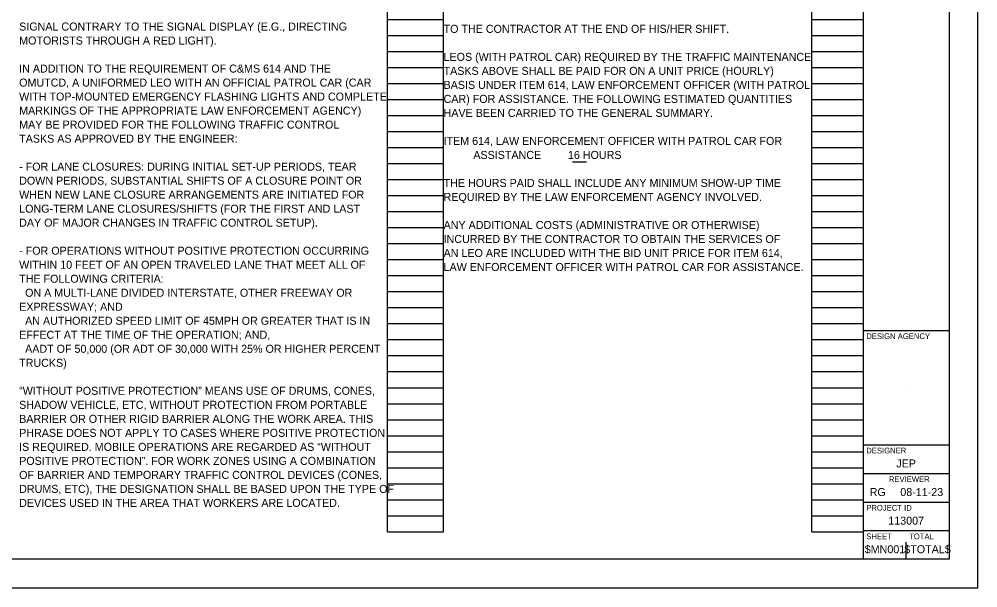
# Model space of a CAD drawing. Extents: x 0 to 69, y 0 to 22.
# Drawn here: x 17.24 to 34, y 0 to 9.94 of the extents above; entities that cross this region are included whole.
import ezdxf

# ---------------------------------------------------------------- set-up
doc = ezdxf.new("R2010")
doc.units = 0
for name, color, linetype in [('GM_X_City_Street', 7, 'Continuous'), ('GM_X_Corporation_Text', 7, 'Continuous'), ('SH_Border', 7, 'Continuous'), ('SH_Cut_Line', 7, 'Continuous'), ('SH_Data', 7, 'Continuous'), ('SH_Text', 7, 'Continuous')]:
    doc.layers.add(name, color=color, linetype=linetype)

msp = doc.modelspace()

# ---------------------------------------------------------------- linework, layer by layer
at = {"layer": 'GM_X_City_Street'}
for p, q in [((23.68, 0.98), (23.68, 21.14)), ((24.66, 0.98), (24.66, 21.14)), ((31.1, 0.98), (31.1, 21.14)), ((32, 0.98), (32, 21.14)), ((23.68, 9.94), (24.66, 9.94)), ((31.1, 9.94), (32, 9.94)), ((23.68, 9.66), (24.66, 9.66)), ((31.1, 9.66), (32, 9.66)), ((23.68, 9.38), (24.66, 9.38)), ((31.1, 9.38), (32, 9.38)), ((23.68, 9.1), (24.66, 9.1)), ((31.1, 9.1), (32, 9.1)), ((23.68, 8.82), (24.66, 8.82)), ((31.1, 8.82), (32, 8.82)), ((23.68, 8.54), (24.66, 8.54)), ((31.1, 8.54), (32, 8.54)), ((23.68, 8.26), (24.66, 8.26)), ((31.1, 8.26), (32, 8.26)), ((23.68, 7.98), (24.66, 7.98)), ((31.1, 7.98), (32, 7.98)), ((23.68, 7.7), (24.66, 7.7)), ((31.1, 7.7), (32, 7.7)), ((23.68, 7.42), (24.66, 7.42)), ((31.1, 7.42), (32, 7.42)), ((23.68, 7.14), (24.66, 7.14)), ((31.1, 7.14), (32, 7.14)), ((23.68, 6.86), (24.66, 6.86)), ((31.1, 6.86), (32, 6.86)), ((23.68, 6.58), (24.66, 6.58)), ((31.1, 6.58), (32, 6.58)), ((23.68, 6.3), (24.66, 6.3)), ((31.1, 6.3), (32, 6.3)), ((23.68, 6.02), (24.66, 6.02)), ((31.1, 6.02), (32, 6.02)), ((23.68, 5.74), (24.66, 5.74)), ((31.1, 5.74), (32, 5.74)), ((23.68, 5.46), (24.66, 5.46)), ((31.1, 5.46), (32, 5.46)), ((23.68, 5.18), (24.66, 5.18)), ((31.1, 5.18), (32, 5.18)), ((23.68, 4.9), (24.66, 4.9)), ((31.1, 4.9), (32, 4.9)), ((23.68, 4.62), (24.66, 4.62)), ((31.1, 4.62), (32, 4.62)), ((23.68, 4.34), (24.66, 4.34)), ((31.1, 4.34), (32, 4.34)), ((23.68, 4.06), (24.66, 4.06)), ((31.1, 4.06), (32, 4.06)), ((23.68, 3.78), (24.66, 3.78)), ((31.1, 3.78), (32, 3.78)), ((23.68, 3.5), (24.66, 3.5)), ((31.1, 3.5), (32, 3.5)), ((23.68, 3.22), (24.66, 3.22)), ((31.1, 3.22), (32, 3.22)), ((23.68, 2.94), (24.66, 2.94)), ((31.1, 2.94), (32, 2.94)), ((23.68, 2.66), (24.66, 2.66)), ((31.1, 2.66), (32, 2.66)), ((23.68, 2.38), (24.66, 2.38)), ((31.1, 2.38), (32, 2.38)), ((23.68, 2.1), (24.66, 2.1)), ((31.1, 2.1), (32, 2.1)), ((23.68, 1.82), (24.66, 1.82)), ((31.1, 1.82), (32, 1.82)), ((23.68, 1.54), (24.66, 1.54)), ((31.1, 1.54), (32, 1.54)), ((23.68, 1.26), (24.66, 1.26)), ((31.1, 1.26), (32, 1.26)), ((23.68, 0.98), (24.66, 0.98)), ((31.1, 0.98), (32, 0.98))]:
    msp.add_line(p, q, dxfattribs=at)
at = {"layer": 'GM_X_Corporation_Text'}
msp.add_line((26.916, 7.45), (27.16, 7.45), dxfattribs=at)
at = {"layer": 'SH_Border'}
for p, q in [((32, 0.5), (32, 21.5)), ((32, 4.5), (33.5, 4.5)), ((32, 2.5), (33.5, 2.5)), ((32, 2), (33.5, 2)), ((32, 1.5), (33.5, 1.5)), ((32, 1), (33.5, 1))]:
    msp.add_line(p, q, dxfattribs=at)
msp.add_lwpolyline([(1.5, 21.5), (33.5, 21.5), (33.5, 0.5), (1.5, 0.5)], close=True, dxfattribs=at)
at = {"layer": 'SH_Cut_Line'}
msp.add_lwpolyline([(0, 0), (34, 0), (34, 22), (0, 22)], close=True, dxfattribs=at)
at = {"layer": 'SH_Data'}
for p, q in [((32.75, 3.5), (32.75, 3.5)), ((32.375, 0.675), (32.375, 0.675)), ((32.75, 0.5), (32.75, 0.8))]:
    msp.add_line(p, q, dxfattribs=at)

# ---------------------------------------------------------------- texts
for s, height, p in [('DESIGN AGENCY', 0.1, (32.05, 4.35)), ('DESIGNER', 0.1, (32.05, 2.35)), ('JEP', 0.14, (32.575, 2.105)), ('REVIEWER', 0.1, (32.445, 1.85)), ('RG', 0.14, (32.109, 1.605)), ('08-11-23', 0.14, (32.645, 1.605)), ('PROJECT ID', 0.1, (32.05, 1.35)), ('113007', 0.14, (32.435, 1.105)), ('SHEET', 0.1, (32.05, 0.85)), ('TOTAL', 0.1, (32.8, 0.85)), ('$MN001', 0.14, (32.023, 0.605)), ('$TOTAL$', 0.14, (32.715, 0.605))]:
    msp.add_text(s, height=height, dxfattribs=at).set_placement(p)
at = {"layer": 'SH_Text'}
for s, p in [('SIGNAL CONTRARY TO THE SIGNAL DISPLAY (E.G., DIRECTING ', (17.24, 9.745)), ('TO THE CONTRACTOR AT THE END OF HIS/HER SHIFT.', (24.66, 9.705)), ('MOTORISTS THROUGH A RED LIGHT).', (17.24, 9.5)), ('LEOS (WITH PATROL CAR) REQUIRED BY THE TRAFFIC MAINTENANCE ', (24.66, 9.215)), ('IN ADDITION TO THE REQUIREMENT OF C&MS 614 AND THE ', (17.24, 9.01)), ('TASKS ABOVE SHALL BE PAID FOR ON A UNIT PRICE (HOURLY) ', (24.66, 8.97)), ('OMUTCD, A UNIFORMED LEO WITH AN OFFICIAL PATROL CAR (CAR ', (17.24, 8.765)), ('BASIS UNDER ITEM 614, LAW ENFORCEMENT OFFICER (WITH PATROL ', (24.66, 8.725)), ('WITH TOP-MOUNTED EMERGENCY FLASHING LIGHTS AND COMPLETE ', (17.24, 8.52)), ('CAR) FOR ASSISTANCE. THE FOLLOWING ESTIMATED QUANTITIES ', (24.66, 8.48)), ('MARKINGS OF THE APPROPRIATE LAW ENFORCEMENT AGENCY) ', (17.24, 8.275)), ('HAVE BEEN CARRIED TO THE GENERAL SUMMARY.', (24.66, 8.235)), ('MAY BE PROVIDED FOR THE FOLLOWING TRAFFIC CONTROL', (17.24, 8.03)), ('TASKS AS APPROVED BY THE ENGINEER:', (17.24, 7.785)), ('ITEM 614, LAW ENFORCEMENT OFFICER WITH PATROL CAR FOR ', (24.66, 7.745)), ('          ASSISTANCE         16 HOURS', (24.66, 7.5)), ('- FOR LANE CLOSURES: DURING INITIAL SET-UP PERIODS, TEAR ', (17.24, 7.295)), ('DOWN PERIODS, SUBSTANTIAL SHIFTS OF A CLOSURE POINT OR ', (17.24, 7.05)), ('THE HOURS PAID SHALL INCLUDE ANY MINIMUM SHOW-UP TIME ', (24.66, 7.01)), ('WHEN NEW LANE CLOSURE ARRANGEMENTS ARE INITIATED FOR ', (17.24, 6.805)), ('REQUIRED BY THE LAW ENFORCEMENT AGENCY INVOLVED.', (24.66, 6.765)), ('LONG-TERM LANE CLOSURES/SHIFTS (FOR THE FIRST AND LAST ', (17.24, 6.56)), ('DAY OF MAJOR CHANGES IN TRAFFIC CONTROL SETUP).', (17.24, 6.315)), ('ANY ADDITIONAL COSTS (ADMINISTRATIVE OR OTHERWISE) ', (24.66, 6.275)), ('INCURRED BY THE CONTRACTOR TO OBTAIN THE SERVICES OF ', (24.66, 6.03)), ('- FOR OPERATIONS WITHOUT POSITIVE PROTECTION OCCURRING ', (17.24, 5.825)), ('AN LEO ARE INCLUDED WITH THE BID UNIT PRICE FOR ITEM 614, ', (24.66, 5.785)), ('WITHIN 10 FEET OF AN OPEN TRAVELED LANE THAT MEET ALL OF ', (17.24, 5.58)), ('LAW ENFORCEMENT OFFICER WITH PATROL CAR FOR ASSISTANCE.', (24.66, 5.54)), ('THE FOLLOWING CRITERIA:', (17.24, 5.335)), ('  ON A MULTI-LANE DIVIDED INTERSTATE, OTHER FREEWAY OR ', (17.24, 5.09)), ('EXPRESSWAY; AND', (17.24, 4.845)), ('  AN AUTHORIZED SPEED LIMIT OF 45MPH OR GREATER THAT IS IN ', (17.24, 4.6)), ('EFFECT AT THE TIME OF THE OPERATION; AND,', (17.24, 4.355)), ('  AADT OF 50,000 (OR ADT OF 30,000 WITH 25% OR HIGHER PERCENT ', (17.24, 4.11)), ('TRUCKS)', (17.24, 3.865)), ('“WITHOUT POSITIVE PROTECTION” MEANS USE OF DRUMS, CONES, ', (17.24, 3.375)), ('SHADOW VEHICLE, ETC, WITHOUT PROTECTION FROM PORTABLE ', (17.24, 3.13)), ('BARRIER OR OTHER RIGID BARRIER ALONG THE WORK AREA. THIS ', (17.24, 2.885)), ('PHRASE DOES NOT APPLY TO CASES WHERE POSITIVE PROTECTION ', (17.24, 2.64)), ('IS REQUIRED. MOBILE OPERATIONS ARE REGARDED AS “WITHOUT ', (17.24, 2.395)), ('POSITIVE PROTECTION”. FOR WORK ZONES USING A COMBINATION ', (17.24, 2.15)), ('OF BARRIER AND TEMPORARY TRAFFIC CONTROL DEVICES (CONES, ', (17.24, 1.905)), ('DRUMS, ETC), THE DESIGNATION SHALL BE BASED UPON THE TYPE OF ', (17.24, 1.66)), ('DEVICES USED IN THE AREA THAT WORKERS ARE LOCATED.', (17.24, 1.415))]:
    msp.add_text(s, height=0.14, dxfattribs=at).set_placement(p)

doc.saveas('drawing.dxf')
